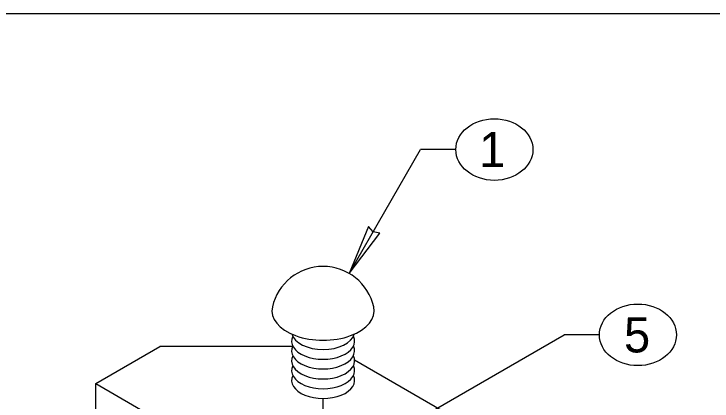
# Model space of a CAD drawing. Extents: x 99862 to 104211, y 98939 to 105076.
# Drawn here: x 101377.4 to 101694.4, y 101899.6 to 102075.5 of the extents above; entities that cross this region are included whole.
import ezdxf

# ---------------------------------------------------------------- set-up
doc = ezdxf.new("R2010")
doc.units = 0
for name, color, linetype in [('Level 1', 7, 'Continuous'), ('Level 15', 7, 'Continuous'), ('Level 20', 7, 'Continuous'), ('Level 26', 7, 'Continuous')]:
    doc.layers.add(name, color=color, linetype=linetype)

msp = doc.modelspace()

# ---------------------------------------------------------------- linework, layer by layer
at = {"layer": 'Level 1'}
msp.add_lwpolyline([(99862, 99999.5), (103151, 99999.5), (103151, 102075.5), (99862, 102075.5)], close=True, dxfattribs=at)
msp.add_arc((101517.77, 101937.18), 23.6, 12.7466, 167.2534, dxfattribs=at)
for centre, major_axis, start_param, end_param in [((101517.77, 101940.65), (23.21, 0), 3.011722, 6.413056), ((101517.77, 101926.86), (14.31, 0), 2.86885, 6.555928), ((101517.77, 101931.31), (14.31, 0), 3.298138, 6.12664), ((101517.77, 101922.5), (14.31, 0), 2.874311, 6.550467), ((101517.77, 101917.96), (14.31, 0), 2.86338, 6.561398), ((101517.77, 101913.51), (14.31, 0), 2.86885, 6.555928), ((101517.77, 101909.06), (14.31, 0), 2.86885, 6.555928)]:
    msp.add_ellipse(centre, major_axis=major_axis, ratio=0.57735, start_param=start_param, end_param=end_param, dxfattribs=at)
at = {"layer": 'Level 15'}
for p, q in [((101529.57, 101957.62), (101562.07, 102013.91)), ((101578.07, 102013.91), (101562.07, 102013.91)), ((101535.45, 101876.72), (101627.26, 101929.72)), ((101643.26, 101929.72), (101627.26, 101929.72)), ((101517.77, 101857.49), (101517.77, 101900.8))]:
    msp.add_line(p, q, dxfattribs=at)
msp.add_lwpolyline([(101529.57, 101957.62), (101543.57, 101975.9), (101540.46, 101976.48), (101538.4, 101978.88)], close=True, dxfattribs=at)
at = {"layer": 'Level 20'}
for centre in [(101595.57, 102013.91), (101660.76, 101929.72)]:
    msp.add_ellipse(centre, major_axis=(-17.5, 0), ratio=0.8, dxfattribs=at)
at = {"layer": 'Level 26'}
for p, q in [((101414.53, 101907.58), (101443.58, 101924.36)), ((101504.14, 101924.36), (101443.58, 101924.36)), ((101594.59, 101882.14), (101532.07, 101918.24)), ((101414.53, 101830.88), (101414.53, 101907.58)), ((101414.53, 101907.58), (101555.95, 101825.93))]:
    msp.add_line(p, q, dxfattribs=at)

# ---------------------------------------------------------------- texts
at = {"layer": 'Level 20'}
for s, p in [('1', (101588.7, 102005.91)), ('5', (101654.45, 101921.73))]:
    msp.add_text(s, height=16, dxfattribs=at).set_placement(p)

doc.saveas('drawing.dxf')
